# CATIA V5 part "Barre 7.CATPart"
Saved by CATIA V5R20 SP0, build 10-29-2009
Part number: Barre 7
Bounding box of the stored display mesh (mm): x -10 to 10, y -180 to 180, z 0 to 10
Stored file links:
  C:\Users\Matthieu\Desktop\IFMA\Cours 2A\Thinkmotion\Projet_IAO_714_Matthieu_Perrusset\Barre 7.CATPart
  C:\Users\Matthieu\Desktop\IFMA\Cours 2A\Thinkmotion\Ass_skl_IAO.CATProduct
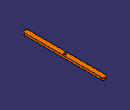
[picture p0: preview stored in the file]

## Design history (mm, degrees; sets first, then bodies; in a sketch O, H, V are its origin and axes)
AxisSystem1: origin (0, 0, 0), X (1, 0, 0), Y (0, 1, 0), Z (0, 0, 1)
Set1
  Plane1 "Plan_Ref": linked copy from another document
  Line1 "Barre_71": linked copy from another document
  Line2 "Axe_Pivot_b7b9": linked copy from another document
  Line3 "Axe_Pivot_b7b8": linked copy from another document
Body1 (main body)
  Sketch1 on Plane1, origin (0, 0, 0), H (1, 0, 0), V (0, 1, 0)
    line L1 (-10, 170) -> (-10, -170)
    arc A1 centre (0, -170) radius 10 from (-10, -170) to (10, -170) ccw
    point P3 (0, -170)
    point P4 (0, -180)
    line L2 (10, -170) -> (10, 170)
    arc A2 centre (0, 170) radius 10 from (10, 170) to (-10, 170) ccw
    point P7 (0, 170)
    reference projected line E1 (0, 170) -> (0, 0) from Line1
    reference projected line E2 (0, 170) -> (0, 0) from Line1
    reference projected point E3 (0, 170) from Line2
    reference projected line E4 (0, 170) -> (0, 0) from Line1
    reference projected line E5 (0, 170) -> (0, 0) from Line1
    reference projected point E6 (0, -170) from Line3
    circle A3 centre (0, 0) radius 5
    distance P7 A2 = 10
    distance L1 E4 = 10
    distance E5 L2 = 10
    distance P3 A1 = 10
    radius A3 = 5
    vertical: L1 V, L2 V
    coincidence: A1 P4, P4 V, P7 E3, P3 E6
    parallelism: E1 L2, L1 E2
  Pad1: profile Sketch1, direction (0, 0, 1), length 10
